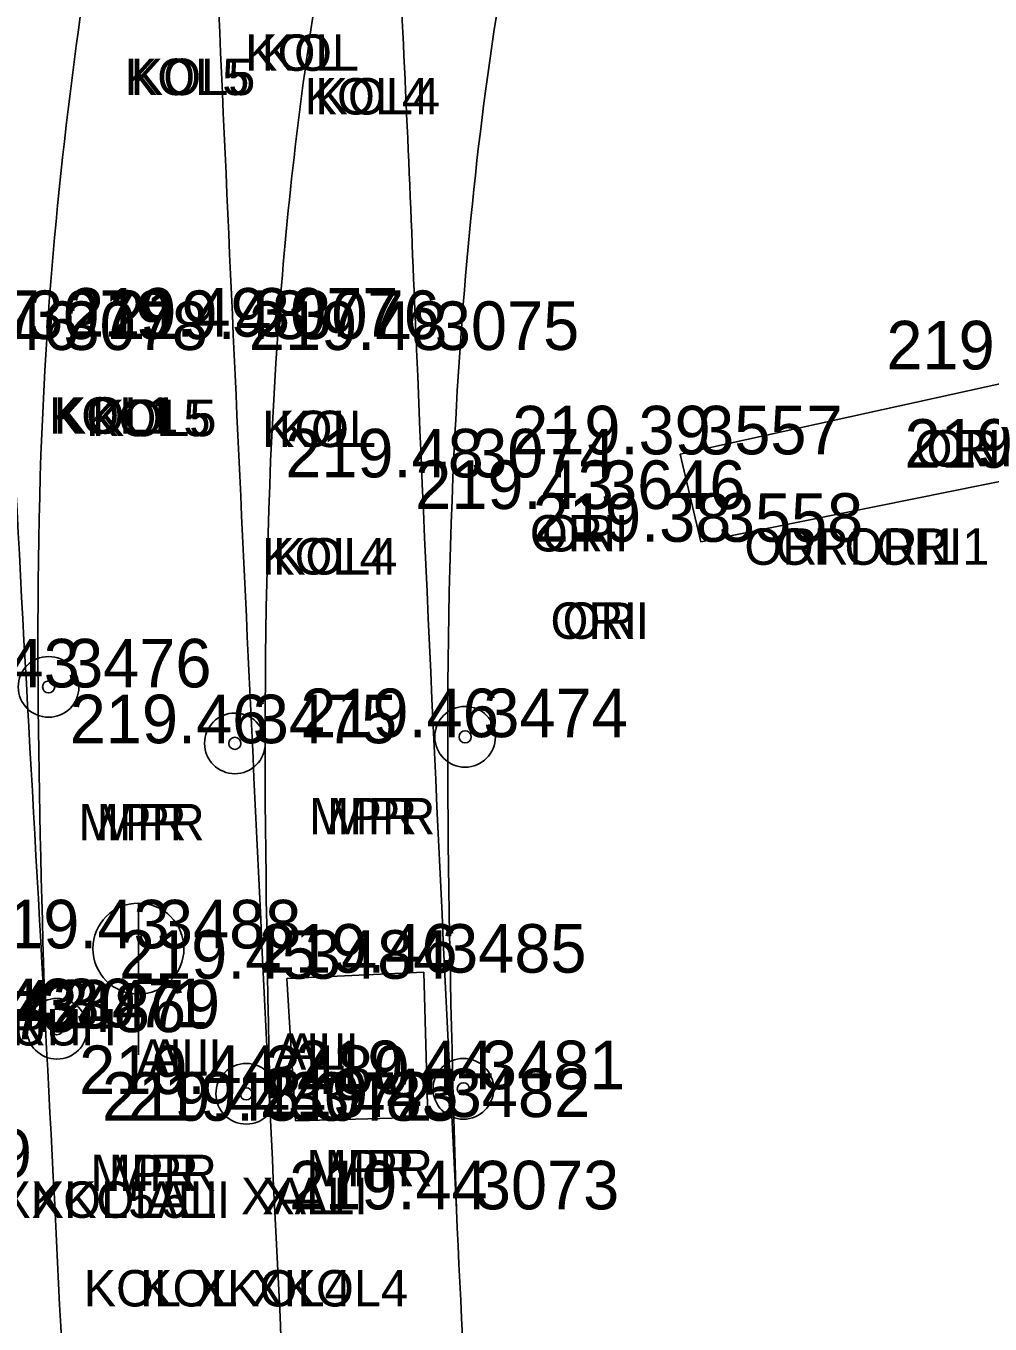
# Model space of a CAD drawing. Extents: x -471047 to -470889, y -1102859 to -1102000.
# Drawn here: x -470923.68 to -470915.74, y -1102055.64 to -1102044.95 of the extents above; entities that cross this region are included whole.
import ezdxf

# ---------------------------------------------------------------- set-up
doc = ezdxf.new("R2010")
doc.units = 0
for name, color, linetype in [('Vrstva 1', 7, 'Continuous'), ('Vrstva 20', 7, 'Continuous'), ('Vrstva 25', 7, 'Continuous'), ('Vrstva 26', 7, 'Continuous'), ('Vrstva 29', 7, 'Continuous'), ('Vrstva 34', 7, 'Continuous'), ('Vrstva 35', 7, 'Continuous'), ('Vrstva 36', 7, 'Continuous'), ('Vrstva 38', 7, 'Continuous')]:
    doc.layers.add(name, color=color, linetype=linetype)

msp = doc.modelspace()

# ---------------------------------------------------------------- linework, layer by layer
at = {"layer": 'Vrstva 1'}
for points in [[(-470924.855, -1102053.304), (-470925.006, -1102047.44), (-470924.123, -1102041.506), (-470922.637, -1102034.36), (-470921.774, -1102030.337), (-470920.687, -1102025.449), (-470919.997, -1102022.703), (-470918.77, -1102018.928), (-470917.254, -1102015.371), (-470916.33, -1102013.583), (-470913.099, -1102008.664), (-470909.896, -1102004.881), (-470905.226, -1102000.466)], [(-470923.521, -1102053.19), (-470923.515, -1102047.615), (-470923.001, -1102043.415), (-470922.299, -1102039.934), (-470921.125, -1102034.455), (-470919.397, -1102026.547), (-470918.535, -1102023.012), (-470917.347, -1102019.378), (-470915.798, -1102015.782), (-470914.449, -1102013.323), (-470911.548, -1102009.097), (-470908.56, -1102005.632), (-470904.267, -1102001.603)], [(-470921.666, -1102053.966), (-470921.608, -1102047.528), (-470921.293, -1102044.721), (-470920.743, -1102041.873), (-470917.58, -1102027.088), (-470916.659, -1102023.359), (-470915.53, -1102020.079), (-470913.952, -1102016.506), (-470912.424, -1102013.741), (-470909.859, -1102010.048), (-470907.058, -1102006.954), (-470903.015, -1102003.355)], [(-470920.134, -1102054.704), (-470920.162, -1102048.671), (-470919.807, -1102044.881), (-470919.4, -1102042.641), (-470916.141, -1102027.446), (-470915.176, -1102023.614), (-470914.148, -1102020.628), (-470912.596, -1102017.149), (-470911.091, -1102014.432), (-470908.431, -1102010.663), (-470905.799, -1102007.808), (-470902.122, -1102004.556)], [(-471040.344, -1102858.385), (-471031.676, -1102846.187), (-471026.357, -1102838.629), (-471023.212, -1102833.975), (-471019.21, -1102827.465), (-471016.861, -1102823.272), (-471013.099, -1102815.912), (-471010.824, -1102810.955), (-471007.329, -1102802.292), (-471005.34, -1102796.515), (-471002.842, -1102787.838), (-471001.3, -1102780.997), (-471000.19, -1102774.713), (-470999.247, -1102768.204), (-470998.794, -1102764.784), (-470997.199, -1102751.812), (-470994.899, -1102732.807), (-470992.551, -1102713.262), (-470990.326, -1102694.887), (-470988.122, -1102676.57), (-470985.812, -1102657.305), (-470983.537, -1102638.407), (-470981.386, -1102620.622), (-470979.843, -1102608.014), (-470976.377, -1102579.253), (-470972.945, -1102550.69), (-470970.475, -1102530.206), (-470967.905, -1102508.801), (-470965.053, -1102485.131), (-470962.734, -1102465.9), (-470960.173, -1102444.812), (-470957.795, -1102425.103), (-470954.965, -1102401.839), (-470953.834, -1102392.574), (-470952.33, -1102379.985), (-470950.744, -1102366.853), (-470948.978, -1102352.106), (-470947.037, -1102335.844), (-470944.949, -1102318.462), (-470944.013, -1102310.745), (-470942.39, -1102297.267), (-470939.519, -1102273.45), (-470937.593, -1102257.43), (-470936.064, -1102244.81), (-470934.114, -1102228.634), (-470931.621, -1102207.856), (-470929.536, -1102190.857), (-470926.572, -1102166.31), (-470924.91, -1102152.663), (-470923.413, -1102140.333), (-470921.923, -1102127.669), (-470921.155, -1102120.084), (-470920.446, -1102109.574), (-470919.912, -1102099.137), (-470919.63, -1102088.981), (-470919.523, -1102081.193), (-470919.563, -1102070.395), (-470919.714, -1102064.236), (-470920.134, -1102054.704), (-470920.462, -1102047.615), (-470920.599, -1102044.52), (-470920.743, -1102041.873), (-470921.125, -1102034.455), (-470921.774, -1102030.337), (-470922.418, -1102027.787), (-470923.734, -1102023.93), (-470924.872, -1102021.434), (-470926.752, -1102018.182), (-470927.953, -1102016.45), (-470929.616, -1102014.424), (-470932.252, -1102011.756), (-470935.111, -1102009.425), (-470938.391, -1102007.371), (-470942.651, -1102005.401)], [(-471041.328, -1102857.18), (-471032.144, -1102844.242), (-471027.583, -1102837.763), (-471024.388, -1102833.028), (-471020.451, -1102826.6), (-471018.089, -1102822.378), (-471014.542, -1102815.445), (-471012.233, -1102810.418), (-471009.247, -1102803.108), (-471006.795, -1102796.098), (-471004.315, -1102787.532), (-471002.782, -1102780.723), (-471001.674, -1102774.458), (-471000.75, -1102768.095), (-471000.28, -1102764.601), (-470998.692, -1102751.741), (-470996.378, -1102732.635), (-470994.028, -1102713.058), (-470991.808, -1102694.749), (-470989.616, -1102676.447), (-470987.284, -1102657.013), (-470985.031, -1102638.272), (-470982.87, -1102620.431), (-470981.334, -1102607.933), (-470977.881, -1102579.263), (-470974.429, -1102550.492), (-470971.964, -1102530.054), (-470969.391, -1102508.607), (-470966.54, -1102484.984), (-470964.231, -1102465.853), (-470961.679, -1102444.752), (-470959.304, -1102425.078), (-470956.455, -1102401.634), (-470955.339, -1102392.489), (-470953.812, -1102379.71), (-470952.249, -1102366.808), (-470950.479, -1102352.023), (-470948.536, -1102335.868), (-470946.426, -1102318.233), (-470945.493, -1102310.531), (-470943.864, -1102297.013), (-470940.984, -1102273.071), (-470939.078, -1102257.195), (-470937.559, -1102244.684), (-470935.592, -1102228.353), (-470933.101, -1102207.653), (-470931.011, -1102190.57), (-470928.046, -1102166.021), (-470926.409, -1102152.578), (-470924.898, -1102140.121), (-470923.427, -1102127.544), (-470922.647, -1102119.826), (-470921.919, -1102109.229), (-470921.42, -1102099.134), (-470921.127, -1102089.016), (-470921.023, -1102081.453), (-470921.061, -1102070.468), (-470921.209, -1102064.314), (-470921.666, -1102053.966), (-470922.156, -1102043.345), (-470922.299, -1102039.934), (-470922.637, -1102034.36), (-470923.091, -1102031.241), (-470923.847, -1102028.247), (-470925.083, -1102024.594), (-470926.222, -1102022.086), (-470928.04, -1102018.943), (-470929.138, -1102017.357), (-470930.929, -1102015.175), (-470933.062, -1102013.049), (-470936.379, -1102010.368), (-470939.169, -1102008.662), (-470942.899, -1102006.906), (-470945.661, -1102005.908)], [(-471043.557, -1102855.955), (-471035.129, -1102844.026), (-471029.872, -1102836.499), (-471026.577, -1102831.578), (-471022.675, -1102825.415), (-471020.123, -1102821.053), (-471016.667, -1102814.59), (-471014.208, -1102809.45), (-471011.177, -1102802.451), (-471008.55, -1102795.333), (-471006.082, -1102787.209), (-471004.464, -1102780.376), (-471003.265, -1102774.167), (-471002.327, -1102767.948), (-471001.636, -1102762.527), (-471000.297, -1102751.605), (-470997.959, -1102732.524), (-470995.602, -1102712.802), (-470993.412, -1102694.623), (-470991.21, -1102676.17), (-470988.891, -1102656.857), (-470986.625, -1102638.083), (-470984.455, -1102620.195), (-470982.936, -1102607.733), (-470979.497, -1102579.223), (-470976.023, -1102550.279), (-470973.554, -1102529.822), (-470970.991, -1102508.497), (-470968.146, -1102484.787), (-470965.835, -1102465.72), (-470963.284, -1102444.529), (-470960.91, -1102424.942), (-470958.043, -1102401.343), (-470956.946, -1102392.356), (-470955.396, -1102379.408), (-470953.851, -1102366.636), (-470952.049, -1102351.733), (-470950.124, -1102335.611), (-470948.034, -1102318.083), (-470947.094, -1102310.328), (-470945.421, -1102296.51), (-470942.58, -1102272.848), (-470940.675, -1102256.948), (-470939.176, -1102244.526), (-470937.187, -1102228.174), (-470934.708, -1102207.467), (-470932.621, -1102190.433), (-470929.634, -1102165.778), (-470928.004, -1102152.415), (-470926.45, -1102139.595), (-470925.003, -1102127.418), (-470924.249, -1102119.695), (-470923.515, -1102109.093), (-470923.018, -1102099.069), (-470922.711, -1102088.911), (-470922.643, -1102081.356), (-470922.797, -1102070.414), (-470923.018, -1102064.454), (-470923.52, -1102053.203), (-470923.823, -1102047.529), (-470924.123, -1102041.506), (-470924.462, -1102037.486), (-470924.934, -1102031.904), (-470925.664, -1102028.672), (-470926.771, -1102025.506), (-470927.959, -1102022.914), (-470929.674, -1102020.028), (-470930.76, -1102018.498), (-470932.447, -1102016.478), (-470935.215, -1102013.816), (-470937.644, -1102011.98), (-470940.381, -1102010.371), (-470943.968, -1102008.669), (-470947.145, -1102007.524), (-470950.874, -1102006.74)]]:
    msp.add_spline(points, degree=3, dxfattribs=at)
at = {"layer": 'Vrstva 20'}
for p, q in [((-470915.121, -1102047.782), (-470918.29, -1102048.478)), ((-470918.29, -1102048.478), (-470918.119, -1102049.201)), ((-470918.119, -1102049.201), (-470915.064, -1102048.585))]:
    msp.add_line(p, q, dxfattribs=at)
at = {"layer": 'Vrstva 25'}
for q in [(-470922.754, -1102052.177), (-470922.754, -1102053.427)]:
    msp.add_line((-470922.754, -1102052.927), q, dxfattribs=at)
msp.add_circle((-470922.754, -1102052.552), 0.375, dxfattribs=at)
at = {"layer": 'Vrstva 26'}
for centre, radius in [((-470923.494, -1102050.396), 0.25), ((-470923.494, -1102050.396), 0.05), ((-470920.062, -1102050.807), 0.25), ((-470921.959, -1102050.861), 0.25), ((-470920.062, -1102050.807), 0.05), ((-470921.959, -1102050.861), 0.05), ((-470923.425, -1102053.212), 0.25), ((-470923.425, -1102053.212), 0.05), ((-470920.076, -1102053.707), 0.25), ((-470921.865, -1102053.748), 0.25), ((-470920.076, -1102053.707), 0.05), ((-470921.865, -1102053.748), 0.05)]:
    msp.add_circle(centre, radius, dxfattribs=at)
at = {"layer": 'Vrstva 29'}
for p, q in [((-470921.531, -1102052.797), (-470920.403, -1102052.747)), ((-470921.459, -1102053.97), (-470921.531, -1102052.797)), ((-470920.37, -1102053.94), (-470920.403, -1102052.747)), ((-470920.37, -1102053.94), (-470921.459, -1102053.97))]:
    msp.add_line(p, q, dxfattribs=at)
at = {"layer": 'Vrstva 34'}
for p, q in [((-470921.95, -1102047.51), (-470921.95, -1102047.51)), ((-470921.61, -1102047.53), (-470921.61, -1102047.53)), ((-470923.52, -1102047.62), (-470923.52, -1102047.62)), ((-470920.46, -1102047.62), (-470920.46, -1102047.62)), ((-470918.29, -1102048.48), (-470918.29, -1102048.48)), ((-470920.16, -1102048.67), (-470920.16, -1102048.67)), ((-470919.09, -1102048.93), (-470919.09, -1102048.93)), ((-470918.12, -1102049.2), (-470918.12, -1102049.2)), ((-470923.49, -1102050.4), (-470923.49, -1102050.4)), ((-470921.96, -1102050.86), (-470921.96, -1102050.86)), ((-470920.06, -1102050.81), (-470920.06, -1102050.81)), ((-470922.75, -1102052.55), (-470922.75, -1102052.55)), ((-470921.53, -1102052.8), (-470921.53, -1102052.8)), ((-470920.4, -1102052.75), (-470920.4, -1102052.75)), ((-470923.52, -1102053.2), (-470923.52, -1102053.2)), ((-470923.42, -1102053.21), (-470923.42, -1102053.21)), ((-470921.86, -1102053.75), (-470921.86, -1102053.75)), ((-470920.08, -1102053.71), (-470920.08, -1102053.71)), ((-470921.67, -1102053.97), (-470921.67, -1102053.97)), ((-470921.46, -1102053.97), (-470921.46, -1102053.97)), ((-470920.37, -1102053.94), (-470920.37, -1102053.94)), ((-470920.13, -1102054.7), (-470920.13, -1102054.7))]:
    msp.add_line(p, q, dxfattribs=at)

# ---------------------------------------------------------------- texts
at = {"layer": 'Vrstva 35'}
for s, p in [('KOL', (-470921.875, -1102045.32)), ('KOL', (-470921.739, -1102045.32)), ('KOL5', (-470922.866, -1102045.52)), ('KOL5', (-470922.817, -1102045.52)), ('KOL4', (-470921.385, -1102045.68)), ('KOL4', (-470921.295, -1102045.68)), ('KOL1', (-470923.492, -1102048.31)), ('KOL1', (-470923.45, -1102048.31)), ('KOL5', (-470923.186, -1102048.33)), ('KOL5', (-470923.137, -1102048.33)), ('KOL', (-470921.735, -1102048.42)), ('KOL', (-470921.599, -1102048.42)), ('ORI', (-470916.358, -1102048.58)), ('ORI', (-470916.259, -1102048.58)), ('ORI', (-470919.528, -1102049.28)), ('ORI', (-470919.429, -1102049.28)), ('KOL4', (-470921.735, -1102049.47)), ('KOL4', (-470921.645, -1102049.47)), ('ORI ORI1', (-470917.76, -1102049.39)), ('ORI ORI1', (-470917.502, -1102049.39)), ('ORI', (-470919.358, -1102050)), ('ORI', (-470919.259, -1102050)), ('MPR', (-470921.349, -1102051.61)), ('MPR', (-470921.199, -1102051.61)), ('MPR', (-470923.249, -1102051.66)), ('MPR', (-470923.099, -1102051.66)), ('SKRUH', (-470924.625, -1102053.35)), ('SKRUH', (-470924.339, -1102053.35)), ('ALI', (-470922.768, -1102053.6)), ('ALI', (-470922.669, -1102053.6)), ('ALI', (-470921.638, -1102053.55)), ('ALI', (-470921.539, -1102053.55)), ('MPR', (-470923.149, -1102054.55)), ('MPR', (-470922.999, -1102054.55)), ('MPR', (-470921.369, -1102054.51)), ('MPR', (-470921.219, -1102054.51)), ('KOL1 XKOL5', (-470925.046, -1102054.77)), ('KOL1 XKOL5', (-470924.772, -1102054.77)), ('ALI', (-470922.698, -1102054.77)), ('ALI', (-470922.599, -1102054.77)), ('XALI', (-470921.908, -1102054.74)), ('XALI', (-470921.734, -1102054.74)), ('KOL XKOL4', (-470923.205, -1102055.5)), ('KOL XKOL4', (-470922.74, -1102055.5))]:
    msp.add_text(s, height=0.3, dxfattribs=at).set_placement(p)
at = {"layer": 'Vrstva 36'}
for s, p in [(' 3079', (-470923.82, -1102047.53)), (' 3077', (-470921.95, -1102047.51)), (' 3076', (-470921.61, -1102047.53)), (' 3078', (-470923.52, -1102047.62)), (' 3075', (-470920.46, -1102047.62)), (' 3557', (-470918.29, -1102048.48)), (' 3074', (-470920.16, -1102048.67)), (' 3646', (-470919.09, -1102048.93)), (' 3558', (-470918.12, -1102049.2)), (' 3476', (-470923.49, -1102050.4)), (' 3475', (-470921.96, -1102050.86)), (' 3474', (-470920.06, -1102050.81)), (' 3488', (-470922.75, -1102052.55)), (' 3485', (-470920.4, -1102052.75)), (' 3484', (-470921.53, -1102052.8)), (' 3071', (-470923.52, -1102053.2)), (' 3479', (-470923.42, -1102053.21)), (' 3487', (-470924.85, -1102053.3)), (' 3486', (-470923.7, -1102053.24)), (' 3480', (-470921.86, -1102053.75)), (' 3481', (-470920.08, -1102053.71)), (' 3072', (-470921.67, -1102053.97)), (' 3483', (-470921.46, -1102053.97)), (' 3482', (-470920.37, -1102053.94)), (' 3069', (-470924.97, -1102054.44)), (' 3073', (-470920.13, -1102054.7))]:
    msp.add_text(s, height=0.4, dxfattribs=at).set_placement(p)
at = {"layer": 'Vrstva 38'}
for s, p in [('219.47 ', (-470925.203, -1102047.53)), ('219.49 ', (-470923.334, -1102047.51)), ('219.48 ', (-470922.994, -1102047.53)), ('219.46 ', (-470924.88, -1102047.62)), ('219.48 ', (-470921.844, -1102047.62)), ('219.31 ', (-470916.59, -1102047.78)), ('219.39 ', (-470919.674, -1102048.48)), ('219.32 ', (-470916.441, -1102048.59)), ('219.48 ', (-470921.544, -1102048.67)), ('219.43 ', (-470920.473, -1102048.93)), ('219.38 ', (-470919.504, -1102049.2)), ('219.43 ', (-470924.873, -1102050.4)), ('219.46 ', (-470923.32, -1102050.86)), ('219.46 ', (-470921.42, -1102050.81)), ('219.43 ', (-470924.133, -1102052.55)), ('219.46 ', (-470921.76, -1102052.75)), ('219.45 ', (-470922.914, -1102052.8)), ('219.43 ', (-470924.903, -1102053.2)), ('219.42 ', (-470924.801, -1102053.21)), ('219.44 ', (-470925.082, -1102053.24)), ('219.44 ', (-470923.242, -1102053.75)), ('219.44 ', (-470921.462, -1102053.71)), ('219.45 ', (-470923.054, -1102053.97)), ('219.44 ', (-470922.842, -1102053.97)), ('219.45 ', (-470921.754, -1102053.94)), ('219.44 ', (-470921.512, -1102054.7))]:
    msp.add_text(s, height=0.4, dxfattribs=at).set_placement(p)

doc.saveas('drawing.dxf')
